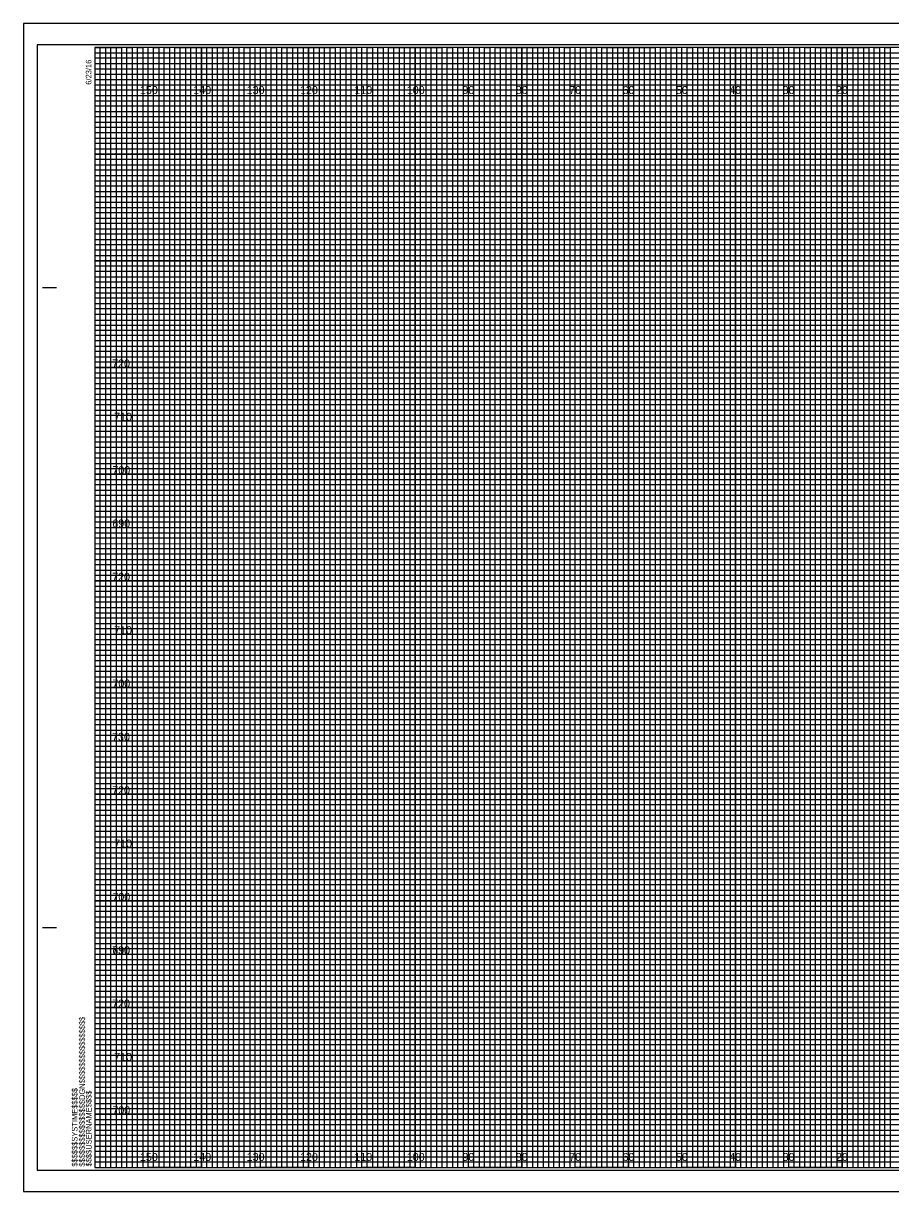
# Model space of a CAD drawing. Extents: x -397 to 323, y -4 to 654.
# Drawn here: x -13.4 to 149.1, y 435.5 to 654.5 of the extents above; entities that cross this region are included whole.
import ezdxf

# ---------------------------------------------------------------- set-up
doc = ezdxf.new("R2010")
doc.units = 0
for name, color, linetype in [('Default', 7, 'Continuous'), ('Prop XS Elevation Labels', 7, 'Continuous'), ('Prop XS Offset Labels', 7, 'Continuous'), ('Sheet Cross Section CELL', 7, 'Continuous'), ('Sheet Cross Section Grid Major CELL', 7, 'Continuous'), ('Sheet Cross Section Grid Middle CELL', 7, 'Continuous'), ('Sheet Cross Section Grid Minor 1 CELL', 7, 'Continuous'), ('Sheet Cross Section Grid Minor 2 CELL', 7, 'Continuous'), ('Sheet Cutting Line CELL', 7, 'Continuous'), ('Sheet DOT Grid CELL', 7, 'Continuous'), ('Sheet Plot Border Inside CELL', 7, 'Continuous'), ('Sheet Plot Border Outside CELL', 7, 'Continuous')]:
    doc.layers.add(name, color=color, linetype=linetype)

msp = doc.modelspace()

# ---------------------------------------------------------------- linework, layer by layer
at = {"layer": 'Default'}
msp.add_lwpolyline([(-13.4, 435.5), (323.3, 435.5), (323.3, 654.5), (-13.4, 654.5)], close=True, dxfattribs=at)
at = {"layer": 'Sheet Cross Section CELL'}
for p, q in [((-9.8, 605), (-7.3, 605)), ((-9.7, 605), (-7.2, 605)), ((-9.8, 485), (-7.3, 485)), ((-9.7, 485), (-7.2, 485)), ((0, 440), (0, 440)), ((0, 440), (0, 440)), ((0, 440), (0, 440)), ((0, 440), (0, 440)), ((0, 440), (0, 440)), ((0, 440), (0, 440)), ((0, 440), (0, 440))]:
    msp.add_line(p, q, dxfattribs=at)
msp.add_lwpolyline([(320, 650), (0, 650), (0, 440), (320, 440)], close=True, dxfattribs=at)
at = {"layer": 'Sheet Cross Section Grid Major CELL'}
for p, q in [((10, 650), (0, 650)), ((10, 440), (10, 650)), ((30, 650), (20, 650)), ((20, 650), (20, 440)), ((30, 440), (30, 650)), ((50, 650), (40, 650)), ((40, 650), (40, 440)), ((50, 440), (50, 650)), ((70, 650), (60, 650)), ((60, 650), (60, 440)), ((70, 440), (70, 650)), ((90, 650), (80, 650)), ((80, 650), (80, 440)), ((90, 440), (90, 650)), ((110, 650), (100, 650)), ((100, 650), (100, 440)), ((110, 440), (110, 650)), ((130, 650), (120, 650)), ((120, 650), (120, 440)), ((130, 440), (130, 650)), ((150, 650), (140, 650)), ((140, 650), (140, 440)), ((20, 440), (10, 440)), ((40, 440), (30, 440)), ((60, 440), (50, 440)), ((80, 440), (70, 440)), ((100, 440), (90, 440)), ((120, 440), (110, 440)), ((140, 440), (130, 440))]:
    msp.add_line(p, q, dxfattribs=at)
for points in [[(0, 640), (320, 640), (320, 630), (0, 630)], [(0, 620), (320, 620), (320, 610), (0, 610)], [(0, 600), (320, 600), (320, 590), (0, 590)], [(0, 580), (320, 580), (320, 570), (0, 570)], [(0, 560), (320, 560), (320, 550), (0, 550)], [(0, 540), (320, 540), (320, 530), (0, 530)], [(0, 520), (320, 520), (320, 510), (0, 510)], [(0, 500), (320, 500), (320, 490), (0, 490)], [(0, 480), (320, 480), (320, 470), (0, 470)], [(0, 460), (320, 460), (320, 450), (0, 450)]]:
    msp.add_lwpolyline(points, dxfattribs=at)
at = {"layer": 'Sheet Cross Section Grid Middle CELL'}
for points in [[(0, 650), (5, 650), (5, 440), (15, 440), (15, 650), (25, 650), (25, 440), (35, 440), (35, 650), (45, 650), (45, 440), (55, 440), (55, 650), (65, 650), (65, 440), (75, 440), (75, 650), (85, 650), (85, 440), (95, 440), (95, 650), (105, 650), (105, 440), (115, 440), (115, 650), (125, 650), (125, 440), (135, 440), (135, 650), (145, 650), (145, 440), (155, 440)], [(0, 645), (275, 645)], [(0, 625), (320, 625), (320, 635), (0, 635)], [(0, 605), (320, 605), (320, 615), (0, 615)], [(0, 585), (320, 585), (320, 595), (0, 595)], [(0, 565), (320, 565), (320, 575), (0, 575)], [(0, 545), (320, 545), (320, 555), (0, 555)], [(0, 525), (320, 525), (320, 535), (0, 535)], [(0, 505), (320, 505), (320, 515), (0, 515)], [(0, 485), (320, 485), (320, 495), (0, 495)], [(0, 465), (320, 465), (320, 475), (0, 475)], [(0, 445), (320, 445), (320, 455), (0, 455)]]:
    msp.add_lwpolyline(points, dxfattribs=at)
at = {"layer": 'Sheet Cross Section Grid Minor 1 CELL'}
for p, q in [((0, 649), (260, 649)), ((260, 647.98), (0, 647.98)), ((0, 647.98), (0, 647)), ((0, 647), (260, 647)), ((260, 645.89), (0, 645.89)), ((0, 645.89), (0, 644)), ((0, 644), (320, 644))]:
    msp.add_line(p, q, dxfattribs=at)
for points in [[(0, 643), (270, 643), (320, 643), (320, 642), (0, 642)], [(0, 641), (320, 641), (320, 639), (0, 639)], [(0, 638), (320, 638), (320, 637), (0, 636.98)], [(0, 636), (320, 636), (320, 634), (0, 634)], [(0, 633), (320, 633), (320, 632), (0, 632)], [(0, 631), (320, 631), (320, 629), (0, 629)], [(0, 628), (320, 628), (320, 627), (0, 627)], [(0, 626), (320, 626), (320, 624), (0, 624)], [(0, 623), (320, 623), (320, 622), (0, 622)], [(0, 621), (320, 621), (320, 619), (0, 619)], [(0, 618), (320, 618), (320, 617), (0, 617)], [(0, 616), (320, 616), (320, 613.95), (320, 613), (320, 612), (0, 612)], [(0, 614), (320, 614), (320, 613), (0, 613)], [(0, 611), (320, 611), (320, 609), (0, 609.03)], [(0, 609.03), (320, 609), (320, 608), (0, 608)], [(0, 607), (320, 607), (320, 606), (0, 606)], [(0, 604), (320, 604), (320, 603), (0, 603)], [(0, 602), (320, 602), (320, 601), (0, 601)], [(-0.07, 598.89), (320, 598.89), (320, 597.88), (-0.07, 597.88)], [(0, 597), (320, 597), (320, 596), (0, 596)], [(0, 594), (320, 594), (320, 593), (0, 593)], [(0, 592), (320, 592), (320, 591), (0, 591)], [(0, 589), (320, 589), (320, 588), (0, 588)], [(0, 587), (320, 587), (320, 586), (0, 586)], [(0, 584), (320, 584), (320, 583), (0, 583)], [(0, 582), (320, 582), (320, 581), (0, 581)], [(0, 579), (320, 579), (319.99, 577.98), (0, 578)], [(0, 577), (320, 577), (320, 576), (0, 576)], [(0, 574), (320, 574), (320, 573), (0, 573)], [(0, 572), (320, 572), (320, 571), (0, 571)], [(0, 569), (320, 569), (320, 568), (0, 568)], [(0, 567), (320, 567), (320, 566), (0, 566)], [(0, 564), (320, 564), (320, 563), (0, 563)], [(0, 562), (320, 562), (320, 561), (0, 561)], [(0, 559), (320, 559), (320, 558), (0, 558)], [(0, 556.99), (320.07, 556.91), (320, 556), (0, 556)], [(0, 554), (320, 554), (320, 553), (0, 553)], [(0, 552), (320, 552), (320, 551), (0, 551)], [(0, 549), (320, 549), (320, 548), (0, 548)], [(0, 547), (320, 547), (320, 546), (0, 546)], [(0, 544), (320, 544), (320, 543), (0, 543)], [(0, 542), (320, 542), (320, 541), (0, 541)], [(0, 539), (320, 539), (320, 538), (0, 538)], [(0, 537), (320, 537), (320, 536), (0, 536)], [(0, 534), (320, 534), (320, 533), (0, 533)], [(0, 532), (320, 532), (320, 531), (0, 531)], [(0, 529), (320, 529), (320, 528), (0, 528)], [(0, 527), (320, 527), (320, 526), (0, 526)], [(0, 524), (320, 524), (320, 523), (0, 523)], [(0, 522), (320, 522), (320, 521), (0, 521)], [(0, 519), (320, 519), (319.99, 517.98), (0, 518)], [(0, 517), (320, 517), (320, 516), (0, 516)], [(0, 514), (320, 514), (320, 513), (0, 513)], [(0, 512), (320, 512), (320, 511), (0, 511)], [(0, 509), (320, 509), (320, 508), (0, 508)], [(0, 507), (320, 507), (320, 506), (0, 506)], [(0, 504), (320, 504), (320, 503), (0, 503)], [(0, 502), (320, 502), (320, 501), (0, 501)], [(0, 499), (320, 499), (320, 498), (0, 498)], [(0, 496.99), (320.07, 496.91), (320, 496), (0, 496)], [(0, 494), (320, 494), (320, 493), (0, 493)], [(0, 492), (320, 492), (320, 491), (0, 491)], [(0, 489), (320, 489), (320, 488), (0, 488)], [(0, 487), (320, 487), (320, 486), (0, 486)], [(0, 484), (320, 484), (320, 483), (0, 483)], [(0, 482), (320, 482), (320, 481), (0, 481)], [(0, 479), (320, 479), (320, 478), (0, 478)], [(0, 477), (320, 477), (320, 476), (0, 476)], [(0, 474), (320, 474), (320, 473), (0, 473)], [(0, 472), (320, 472), (320, 471), (0, 471)], [(0, 469), (320, 469), (320, 468), (0, 468)], [(0, 467), (320, 467), (320, 466), (0, 466)], [(0, 464), (320, 464), (320, 463), (0, 463)], [(0, 462), (320, 462), (320, 461), (0, 461)], [(0, 459), (320, 459), (320, 458), (0, 458)], [(0, 457), (320, 457), (320, 456), (0, 456)], [(0, 454), (320, 454), (320, 453), (0, 453)], [(0, 452), (320, 452), (320, 451), (0, 451)], [(0, 449), (320, 449), (320, 448), (0, 448)], [(0, 447), (320, 447), (320, 446), (0, 446)], [(0, 444), (320, 444), (320, 443), (0, 443)], [(0, 442), (320, 442), (320, 441), (0, 441)]]:
    msp.add_lwpolyline(points, dxfattribs=at)
at = {"layer": 'Sheet Cross Section Grid Minor 2 CELL'}
for points in [[(0, 440), (1, 440), (1, 650), (2, 650), (2, 440)], [(2, 440), (3, 440), (3, 650), (4, 650), (4, 440)], [(5, 440), (6, 440), (6, 650), (7, 650), (7, 440)], [(7, 440), (8, 440), (8, 650), (9, 650), (9, 440)], [(10, 440), (11, 440), (11, 650), (12, 650), (12, 440)], [(12, 440), (13, 440), (13, 650), (14, 650), (14, 440)], [(15, 440), (16, 440), (16, 650), (17, 650), (17, 440)], [(17, 440), (18, 440), (18, 650), (19, 650), (19, 440)], [(20, 440), (21, 440), (21, 650), (22, 650), (22, 440)], [(22, 440), (23, 440), (23, 650), (24, 650), (24, 440)], [(25, 440), (26, 440), (26, 650), (27, 650), (27, 440)], [(27, 440), (28, 440), (28, 650), (29, 650), (29, 440)], [(30, 440), (31, 440), (31, 650), (32, 650), (32, 440)], [(32, 440), (33, 440), (33, 650), (34, 650), (34, 440)], [(35, 440), (36, 440), (36, 650), (37, 650), (37, 440)], [(37, 440), (38, 440), (38, 650), (39, 650), (39, 440)], [(40, 440), (41, 440), (41, 650), (42, 650), (42, 440)], [(42, 440), (43, 440), (43, 650), (44, 650), (44, 440)], [(45, 440), (46, 440), (46, 650), (47, 650), (47, 440)], [(47, 440), (48, 440), (48, 650), (49, 650), (49, 440)], [(50, 440), (51, 440), (51, 650), (52, 650), (52, 440)], [(52, 440), (53, 440), (53, 650), (54, 650), (54, 440)], [(55, 440), (56, 440), (56, 650), (57, 650), (57, 440)], [(57, 440), (58, 440), (58, 650), (59, 650), (59, 440)], [(60, 440), (61, 440), (61, 650), (62, 650), (62, 440)], [(62, 440), (63, 440), (63, 650), (64, 650), (64, 440)], [(65, 440), (66, 440), (66, 650), (67, 650), (67, 440)], [(67, 440), (68, 440), (68, 650), (69, 650), (69, 440)], [(70, 440), (71, 440), (71, 650), (72, 650), (72, 440)], [(72, 440), (73, 440), (73, 650), (74, 650), (74, 440)], [(75, 440), (76, 440), (76, 650), (77, 650), (77, 440)], [(77, 440), (78, 440), (78, 650), (79, 650), (79, 440)], [(80, 440), (81, 440), (81, 650), (82, 650), (82, 440)], [(82, 440), (83, 440), (83, 650), (84, 650), (84, 440)], [(85, 440), (86, 440), (86, 650), (87, 650), (87, 440)], [(87, 440), (88, 440), (88, 650), (89, 650), (89, 440)], [(90, 440), (91, 440), (91, 650), (92, 650), (92, 440)], [(92, 440), (93, 440), (93, 650), (94, 650), (94, 440)], [(95, 440), (96, 440), (96, 650), (97, 650), (97, 440)], [(97, 440), (98, 440), (98, 650), (99, 650), (99, 440)], [(100, 440), (101, 440), (101, 650), (102, 650), (102, 440)], [(102, 440), (103, 440), (103, 650), (104, 650), (104, 440)], [(105, 440), (106, 440), (106, 650), (107, 650), (107, 440)], [(107, 440), (108, 440), (108, 650), (109, 650), (109, 440)], [(110, 440), (111, 440), (111, 650), (112, 650), (112, 440)], [(112, 440), (113, 440), (113, 650), (114, 650), (114, 440)], [(115, 440), (116, 440), (116, 650), (117, 650), (117, 440)], [(117, 440), (118, 440), (118, 650), (119, 650), (119, 440)], [(120, 440), (121, 440), (121, 650), (122, 650), (122, 440)], [(122, 440), (123, 440), (123, 650), (124, 650), (124, 440)], [(125, 440), (126, 440), (126, 650), (127, 650), (127, 440)], [(127, 440), (128, 440), (128, 650), (129, 650), (129, 440)], [(130, 440), (131, 440), (131, 650), (132, 650), (132, 440)], [(132, 440), (133, 440), (133, 650), (134, 650), (134, 440)], [(135, 440), (136, 440), (136, 650), (137, 650), (137, 440)], [(137, 440), (138, 440), (138, 650), (139, 650), (139, 440)], [(140, 440), (141, 440), (141, 650), (142, 650), (142, 440)], [(142, 440), (143, 440), (143, 650), (144, 650), (144, 440)], [(145, 440), (146, 440), (146, 650), (147, 650), (147, 440)], [(147, 440), (148, 440), (148, 650), (149, 650), (149, 440)]]:
    msp.add_lwpolyline(points, dxfattribs=at)
at = {"layer": 'Sheet Cutting Line CELL'}
for p, q in [((323.3, 654.5), (-13.4, 654.5)), ((-13.4, 654.5), (-13.4, 435.5)), ((-13.4, 435.5), (323.3, 435.5))]:
    msp.add_line(p, q, dxfattribs=at)
at = {"layer": 'Sheet DOT Grid CELL'}
for p, q in [((10, 440), (10, 650)), ((20, 440), (20, 650)), ((30, 440), (30, 650)), ((40, 440), (40, 650)), ((50, 440), (50, 650)), ((60, 440), (60, 650)), ((70, 440), (70, 650)), ((80, 440), (80, 650)), ((90, 440), (90, 650)), ((100, 440), (100, 650)), ((110, 440), (110, 650)), ((120, 440), (120, 650)), ((130, 440), (130, 650)), ((140, 440), (140, 650)), ((0, 640), (320, 640)), ((0, 630), (320, 630)), ((0, 620), (320, 620)), ((0, 610), (320, 610)), ((0, 600), (320, 600)), ((0, 590), (320, 590)), ((0, 580), (320, 580)), ((0, 570), (320, 570)), ((0, 560), (320, 560)), ((0, 550), (320, 550)), ((0, 540), (320, 540)), ((0, 530), (320, 530)), ((0, 520), (320, 520)), ((0, 510), (320, 510)), ((0, 500), (320, 500)), ((0, 490), (320, 490)), ((0, 480), (320, 480)), ((0, 470), (320, 470)), ((0, 460), (320, 460)), ((0, 450), (320, 450))]:
    msp.add_line(p, q, dxfattribs=at)
at = {"layer": 'Sheet Plot Border Inside CELL'}
msp.add_lwpolyline([(-10.8, 439.5), (322.4, 439.5), (322.4, 650.5), (-10.8, 650.5)], close=True, dxfattribs=at)
at = {"layer": 'Sheet Plot Border Outside CELL'}
msp.add_lwpolyline([(-13.4, 435.5), (323.3, 435.5), (323.3, 654.5), (-13.4, 654.5)], close=True, dxfattribs=at)

# ---------------------------------------------------------------- texts
at = {"layer": 'Prop XS Elevation Labels'}
for s, p in [('720', (3.23, 590)), ('710', (3.61, 580)), ('700', (3.28, 570)), ('690', (3.26, 560)), ('720', (3.23, 550)), ('710', (3.61, 540)), ('700', (3.28, 530)), ('730', (3.22, 520)), ('720', (3.23, 510)), ('710', (3.61, 500)), ('700', (3.28, 490)), ('730', (3.22, 480)), ('690', (3.26, 480)), ('720', (3.23, 470)), ('710', (3.61, 460)), ('700', (3.28, 450))]:
    msp.add_text(s, height=1.5, dxfattribs=at).set_placement(p)
at = {"layer": 'Prop XS Offset Labels'}
for s, p in [('150', (8.44, 641.25)), ('140', (18.44, 641.25)), ('130', (28.44, 641.25)), ('120', (38.44, 641.25)), ('110', (48.62, 641.25)), ('100', (58.44, 641.25)), ('90', (68.86, 641.25)), ('80', (78.86, 641.25)), ('70', (88.86, 641.25)), ('60', (98.86, 641.25)), ('50', (108.86, 641.25)), ('40', (118.86, 641.25)), ('30', (128.86, 641.25)), ('20', (138.86, 641.25)), ('150', (8.44, 441.25)), ('140', (18.44, 441.25)), ('130', (28.44, 441.25)), ('120', (38.44, 441.25)), ('110', (48.62, 441.25)), ('100', (58.44, 441.25)), ('90', (68.86, 441.25)), ('80', (78.86, 441.25)), ('70', (88.86, 441.25)), ('60', (98.86, 441.25)), ('50', (108.86, 441.25)), ('40', (118.86, 441.25)), ('30', (128.86, 441.25)), ('20', (138.86, 441.25))]:
    msp.add_text(s, height=1.5, dxfattribs=at).set_placement(p)
at = {"layer": 'Sheet Cross Section CELL'}
for s, p in [('6/23/16', (-0.65, 643)), ('$$$$$$$$$$$$$$$$DGN$$$$$$$$$$$$$$$$', (-1.88, 440.18)), ('$$$$$$SYSTIME$$$$$', (-3.26, 440.18)), ('$$$$USERNAME$$$$', (-0.62, 440.23))]:
    msp.add_text(s, height=1.05, rotation=90, dxfattribs=at).set_placement(p)

doc.saveas('drawing.dxf')
